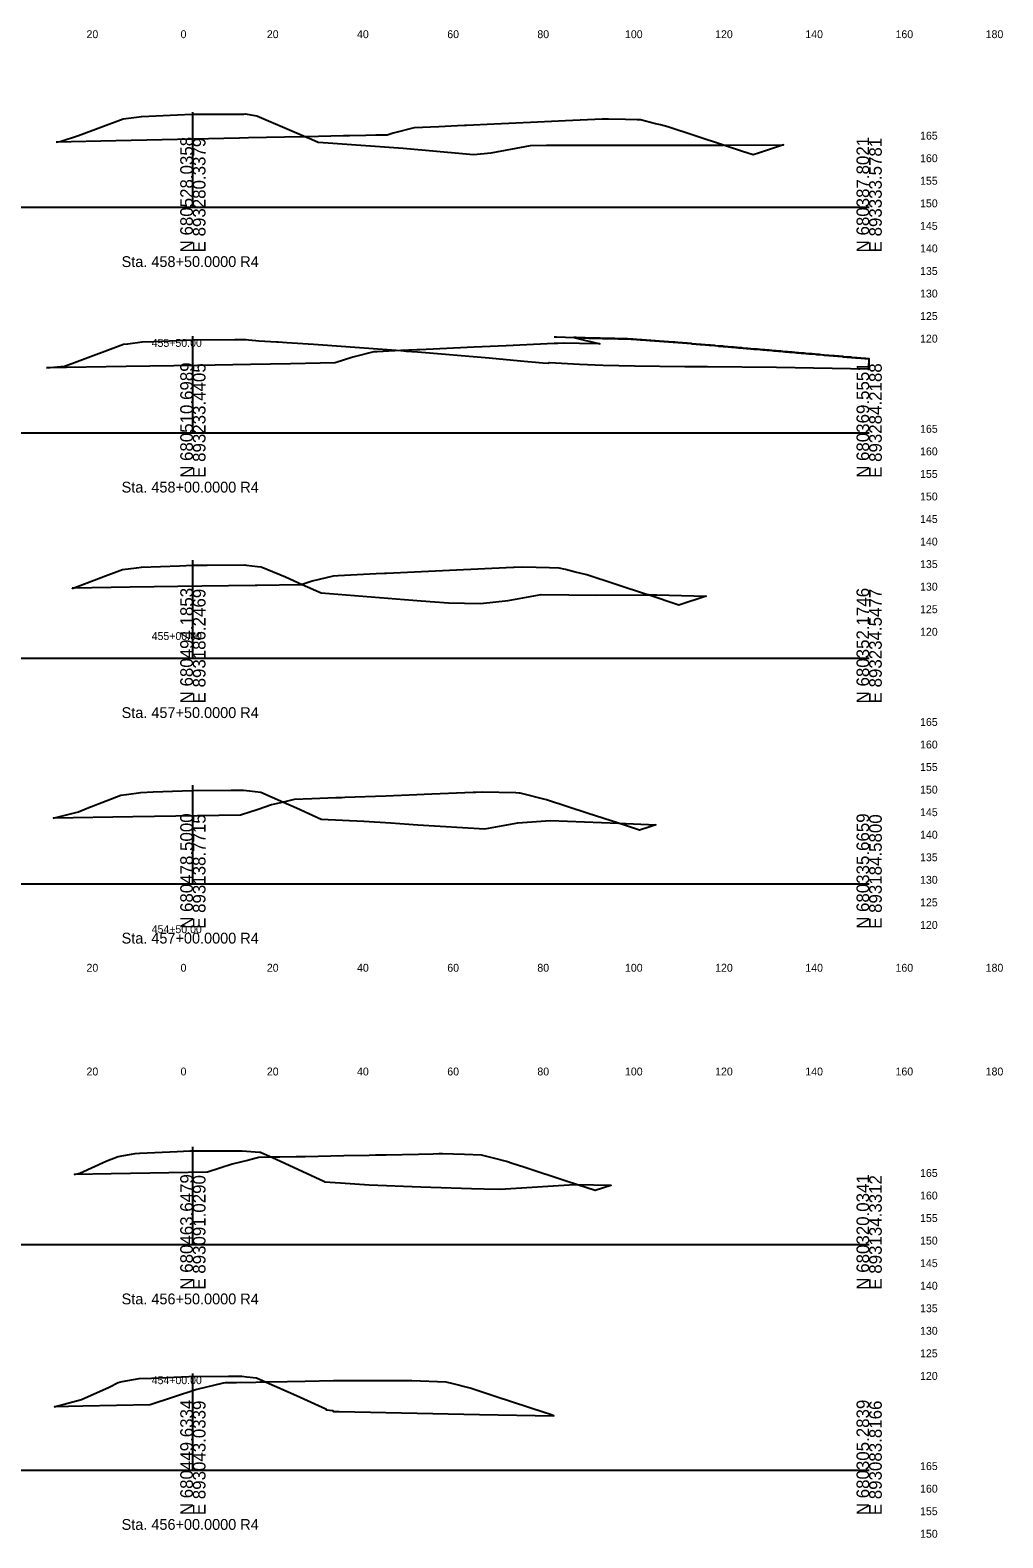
# Model space of a CAD drawing. Extents: x 21059 to 22955, y 6470 to 17494.
# Drawn here: x 21608.7 to 21824.5, y 7499.8 to 7834.1 of the extents above; entities that cross this region are included whole.
import ezdxf

# ---------------------------------------------------------------- set-up
doc = ezdxf.new("R2010")
doc.units = 0
for name, color, linetype in [('CONST_DCH', 7, 'Continuous'), ('Draft_XS_Grid', 7, 'Continuous'), ('Draft_XS_Text', 7, 'Continuous'), ('DTM CONTOURS_MAJOR', 7, 'Continuous'), ('SLOPE_STAKES_FILL', 7, 'Continuous'), ('X_PROFILES_1', 7, 'Continuous'), ('XS_P_TX_CLEARZONE', 7, 'Continuous'), ('XS_SHEET_EW_TX_VOLUME', 7, 'Continuous')]:
    doc.layers.add(name, color=color, linetype=linetype)

msp = doc.modelspace()

# ---------------------------------------------------------------- linework, layer by layer
at = {"layer": 'DTM CONTOURS_MAJOR'}
for p, q in [((21644.84, 7794.84), (21644.84, 7815.91)), ((21494.84, 7794.84), (21644.84, 7794.84)), ((21644.84, 7794.84), (21794.84, 7794.84)), ((21644.84, 7744.84), (21644.84, 7766.24)), ((21494.84, 7744.84), (21644.84, 7744.84)), ((21644.84, 7744.84), (21794.84, 7744.84)), ((21644.84, 7694.84), (21644.84, 7716.56)), ((21494.84, 7694.84), (21644.84, 7694.84)), ((21644.84, 7694.84), (21794.84, 7694.84)), ((21644.84, 7644.84), (21644.84, 7666.7)), ((21494.84, 7644.84), (21644.84, 7644.84)), ((21644.84, 7644.84), (21794.84, 7644.84)), ((21644.84, 7564.84), (21644.84, 7586.54)), ((21494.84, 7564.84), (21644.84, 7564.84)), ((21644.84, 7564.84), (21794.84, 7564.84)), ((21644.84, 7514.84), (21644.84, 7536.27)), ((21494.84, 7514.84), (21644.84, 7514.84)), ((21644.84, 7514.84), (21794.84, 7514.84))]:
    msp.add_line(p, q, dxfattribs=at)
at = {"layer": 'XS_P_TX_CLEARZONE'}
msp.add_lwpolyline([(21724.99, 7766.12), (21725.52, 7766.11), (21725.53, 7766.11), (21731.39, 7765.87), (21732.01, 7765.86), (21732.64, 7765.85), (21733.21, 7765.82), (21733.84, 7765.81), (21734.49, 7765.8), (21735.16, 7765.79), (21735.69, 7765.77), (21736.36, 7765.76), (21737.06, 7765.75), (21737.57, 7765.73), (21738.27, 7765.72), (21738.45, 7765.71), (21739.18, 7765.7), (21739.2, 7765.7), (21739.46, 7765.7), (21740.21, 7765.69), (21740.46, 7765.68), (21741.23, 7765.67), (21742.03, 7765.61), (21742.24, 7765.6), (21742.44, 7765.58), (21743.26, 7765.52), (21744.11, 7765.46), (21744.27, 7765.45), (21744.43, 7765.44), (21745.29, 7765.38), (21746.18, 7765.31), (21746.3, 7765.3), (21746.42, 7765.3), (21747.32, 7765.23), (21747.41, 7765.22), (21748.33, 7765.16), (21749.29, 7765.09), (21749.35, 7765.09), (21749.4, 7765.08), (21750.36, 7765.01), (21751.37, 7764.94), (21751.38, 7764.94), (21751.38, 7764.94), (21751.73, 7764.91), (21752.38, 7764.86), (21752.39, 7764.86), (21752.41, 7764.86), (21753.41, 7764.77), (21753.44, 7764.77), (21754.42, 7764.68), (21755.36, 7764.6), (21755.44, 7764.6), (21755.52, 7764.59), (21756.45, 7764.51), (21757.34, 7764.43), (21757.47, 7764.42), (21757.59, 7764.41), (21758.48, 7764.34), (21759.33, 7764.26), (21759.5, 7764.25), (21759.67, 7764.23), (21760.51, 7764.16), (21761.32, 7764.09), (21761.53, 7764.07), (21762.31, 7764.01), (21762.54, 7763.99), (21762.78, 7763.97), (21763.56, 7763.9), (21764.3, 7763.84), (21764.57, 7763.81), (21765.29, 7763.75), (21765.59, 7763.73), (21765.89, 7763.7), (21766.6, 7763.64), (21766.93, 7763.61), (21767.61, 7763.55), (21768.27, 7763.5), (21768.63, 7763.47), (21769.26, 7763.41), (21769.64, 7763.38), (21770.04, 7763.35), (21770.66, 7763.29), (21771.25, 7763.24), (21771.67, 7763.21), (21772.12, 7763.17), (21772.69, 7763.12), (21773.24, 7763.07), (21773.7, 7763.03), (21774.19, 7762.99), (21774.72, 7762.94), (21775.23, 7762.9), (21775.73, 7762.86), (21776.22, 7762.82), (21776.75, 7762.77), (21777.21, 7762.73), (21777.76, 7762.68), (21778.34, 7762.63), (21778.78, 7762.6), (21779.38, 7762.55), (21779.79, 7762.51), (21780.19, 7762.48), (21780.81, 7762.42), (21781.45, 7762.37), (21781.82, 7762.34), (21782.18, 7762.31), (21782.84, 7762.25), (21783.17, 7762.22), (21783.85, 7762.16), (21784.56, 7762.1), (21784.87, 7762.08), (21785.16, 7762.05), (21785.88, 7761.99), (21786.15, 7761.97), (21786.9, 7761.9), (21787.15, 7761.88), (21787.91, 7761.81), (21788.14, 7761.8), (21788.93, 7761.73), (21789.13, 7761.71), (21789.94, 7761.64), (21790.13, 7761.63), (21790.96, 7761.55), (21791.83, 7761.48), (21791.97, 7761.47), (21792.11, 7761.45), (21792.99, 7761.38), (21793.9, 7761.3), (21794, 7761.29), (21794.1, 7761.28), (21794.84, 7761.22)], dxfattribs=at)
at = {"layer": 'XS_SHEET_EW_TX_VOLUME'}
for points in [[(21614.48, 7809.3), (21615.43, 7809.4), (21619.47, 7810.79), (21629.41, 7814.46), (21632.37, 7814.85), (21633.45, 7815), (21641.46, 7815.32), (21644.62, 7815.45), (21654.38, 7815.47), (21656.12, 7815.49), (21656.41, 7815.53), (21658.57, 7815.2), (21659.03, 7815.13), (21669.91, 7810.48), (21669.18, 7810.46), (21657.21, 7810.21), (21655.18, 7810.17), (21651.71, 7810.09), (21627.74, 7809.58)], [(21669.91, 7810.48), (21671.17, 7809.94), (21672.66, 7809.28), (21674.83, 7809.12), (21691.51, 7807.97), (21705.47, 7806.7), (21707.1, 7806.53), (21710.99, 7806.93), (21719.71, 7808.52), (21723.31, 7808.59), (21732.61, 7808.6), (21758.84, 7808.62), (21762.53, 7808.63), (21750.21, 7812.68), (21748.59, 7813.09), (21747.46, 7813.37), (21744.09, 7814.2), (21743.38, 7814.22), (21740.81, 7814.27), (21737.04, 7814.36), (21736, 7814.38), (21735.65, 7814.37), (21733.97, 7814.29), (21727.48, 7813.99), (21719.76, 7813.63), (21711.7, 7813.26), (21705.55, 7812.98), (21705.08, 7812.96), (21703.52, 7812.88), (21699.41, 7812.69), (21693.94, 7812.44), (21689.3, 7811.3), (21687.95, 7810.86), (21685.45, 7810.81), (21683.17, 7810.76), (21679.59, 7810.68), (21678.27, 7810.66)], [(21762.53, 7808.63), (21775.88, 7808.66), (21770.51, 7806.89), (21769.15, 7806.44), (21766.77, 7807.23)], [(21690.99, 7763.05), (21691.07, 7763.05), (21692.13, 7762.95), (21694.67, 7762.75), (21710.53, 7761.43), (21717.49, 7760.81), (21722.47, 7760.35), (21723.75, 7760.3), (21723.96, 7760.4), (21730.63, 7760.04), (21735.86, 7759.84), (21742.82, 7759.67), (21753.97, 7759.51), (21758.99, 7759.53), (21774.3, 7759.37), (21794.84, 7759.01), (21794.84, 7761.22), (21794.1, 7761.28), (21794, 7761.29), (21793.9, 7761.3), (21792.99, 7761.38), (21792.11, 7761.45), (21791.97, 7761.47), (21791.83, 7761.48), (21790.96, 7761.55), (21790.79, 7761.57), (21789.94, 7761.64), (21789.13, 7761.71), (21788.93, 7761.73), (21788.14, 7761.8), (21787.91, 7761.81), (21787.15, 7761.88), (21786.9, 7761.9), (21786.64, 7761.92), (21785.88, 7761.99), (21785.6, 7762.01), (21784.87, 7762.08), (21784.17, 7762.14), (21783.85, 7762.16), (21783.17, 7762.22), (21782.84, 7762.25), (21782.18, 7762.31), (21781.82, 7762.34), (21781.45, 7762.37), (21780.81, 7762.42), (21780.42, 7762.46), (21779.79, 7762.51), (21779.2, 7762.56), (21778.78, 7762.6), (21778.34, 7762.63), (21777.76, 7762.68), (21777.21, 7762.73), (21776.75, 7762.77), (21776.27, 7762.81), (21775.73, 7762.86), (21775.23, 7762.9), (21774.72, 7762.94), (21774.23, 7762.99), (21773.7, 7763.03), (21773.24, 7763.07), (21772.69, 7763.12), (21772.12, 7763.17), (21771.67, 7763.21), (21771.08, 7763.26), (21770.66, 7763.29), (21770.04, 7763.35), (21769.64, 7763.38), (21769.26, 7763.41), (21768.63, 7763.47), (21767.97, 7763.52), (21767.61, 7763.55), (21766.93, 7763.61), (21766.6, 7763.64), (21765.89, 7763.7), (21765.59, 7763.73), (21764.85, 7763.79), (21764.57, 7763.81), (21764.3, 7763.84), (21763.56, 7763.9), (21762.78, 7763.97), (21762.54, 7763.99), (21762.31, 7764.01), (21761.53, 7764.07), (21760.71, 7764.15), (21760.51, 7764.16), (21759.67, 7764.23), (21759.5, 7764.25), (21759.33, 7764.26), (21758.48, 7764.34), (21757.59, 7764.41), (21757.47, 7764.42), (21757.34, 7764.43), (21756.45, 7764.51), (21755.52, 7764.59), (21755.44, 7764.6), (21754.48, 7764.68), (21754.42, 7764.68), (21754.36, 7764.69), (21753.41, 7764.77), (21753.37, 7764.77), (21752.39, 7764.86), (21752.38, 7764.86), (21751.73, 7764.91), (21751.38, 7764.94), (21751.38, 7764.94), (21750.39, 7765.01), (21750.36, 7765.01), (21749.4, 7765.08), (21749.35, 7765.09), (21749.29, 7765.09), (21748.33, 7765.16), (21747.41, 7765.22), (21747.32, 7765.23), (21746.42, 7765.3), (21746.3, 7765.3), (21745.42, 7765.37), (21745.29, 7765.38), (21744.43, 7765.44), (21744.27, 7765.45), (21744.11, 7765.46), (21743.26, 7765.52), (21742.44, 7765.58), (21742.24, 7765.6), (21742.03, 7765.61), (21741.23, 7765.67), (21740.46, 7765.68), (21740.21, 7765.69), (21739.46, 7765.7), (21739.2, 7765.7), (21739.18, 7765.7), (21738.45, 7765.71), (21738.27, 7765.72), (21737.57, 7765.73), (21737.06, 7765.75), (21736.36, 7765.76), (21735.69, 7765.77), (21735.16, 7765.79), (21734.49, 7765.8), (21733.84, 7765.81), (21729.83, 7765.93), (21729.35, 7765.95), (21731.68, 7765.38), (21733.3, 7764.98), (21735.1, 7764.53), (21730.59, 7764.64), (21727.01, 7764.72), (21725.78, 7764.66), (21724.98, 7764.62), (21714.36, 7764.13), (21710.77, 7763.97), (21707.26, 7763.8), (21696.55, 7763.31), (21695.2, 7763.25), (21694.52, 7763.22)], [(21612.38, 7759.21), (21616.4, 7759.64), (21618.56, 7760.45), (21629.43, 7764.46), (21630.38, 7764.59), (21633.57, 7765.01), (21636.15, 7765.11), (21644.81, 7765.45), (21654.13, 7765.5), (21656.68, 7765.52), (21657.19, 7765.45), (21658.77, 7765.31), (21659.45, 7765.2), (21663.42, 7765), (21663.78, 7764.99), (21665.65, 7764.88), (21671.62, 7764.51), (21672.6, 7764.42), (21690.99, 7763.05), (21685.7, 7762.81), (21684.95, 7762.77), (21680.31, 7761.64), (21676.43, 7760.37), (21666.52, 7760.16), (21657.59, 7759.97), (21645.86, 7759.77), (21630.03, 7759.51)], [(21618.22, 7710.38), (21618.3, 7710.39), (21625.47, 7713.11), (21629.24, 7714.5), (21632.36, 7714.9), (21633.46, 7715.04), (21641.85, 7715.35), (21644.81, 7715.47), (21647.98, 7715.48), (21656.33, 7715.53), (21656.66, 7715.49), (21659.19, 7715.19), (21659.99, 7715.12), (21665.38, 7712.87), (21669.11, 7711.23), (21668.9, 7711.16), (21659.13, 7710.99), (21659.04, 7710.99), (21658.62, 7710.99), (21646.83, 7710.81), (21630.95, 7710.57)], [(21669.11, 7711.23), (21673.31, 7709.38), (21695.47, 7707.57), (21701.52, 7707.14), (21708.64, 7706.95), (21714.77, 7707.67), (21722.06, 7709.01), (21734.4, 7708.84), (21745.81, 7708.87), (21745.49, 7708.97), (21732.23, 7713.34), (21729.44, 7714.03), (21727.48, 7714.51), (21726.11, 7714.85), (21723.94, 7714.9), (21718.02, 7715.03), (21716.14, 7714.95), (21715.99, 7714.94), (21715.85, 7714.93), (21701.78, 7714.28), (21687.76, 7713.63), (21687.56, 7713.62), (21687.35, 7713.61), (21685.53, 7713.53), (21677.04, 7713.13), (21675.96, 7713.08), (21671.31, 7711.94)], [(21618.08, 7710.38), (21618.08, 7710.37), (21618.22, 7710.38)], [(21745.81, 7708.87), (21747.73, 7708.87), (21758.69, 7708.62), (21752.61, 7706.63)], [(21613.87, 7659.35), (21619.5, 7660.76), (21621.41, 7661.62), (21628.89, 7664.46), (21630.1, 7664.67), (21633.31, 7665.09), (21636, 7665.2), (21644.63, 7665.51), (21653.3, 7665.56), (21656.07, 7665.58), (21657.4, 7665.47), (21659.91, 7665.17), (21664.96, 7662.95), (21662.31, 7662.31), (21659.29, 7661.32), (21655.4, 7660.05), (21631.51, 7659.65)], [(21664.96, 7662.95), (21667.83, 7661.69), (21673.27, 7659.2), (21682.78, 7658.73), (21688.74, 7658.32), (21694.76, 7657.92), (21709.59, 7657.04), (21716.9, 7658.38), (21724.14, 7658.87), (21739.21, 7658.25), (21732.53, 7660.44), (21723.24, 7663.48), (21717.45, 7664.91), (21717.25, 7664.96), (21716.49, 7664.97), (21709.03, 7665.17), (21707.62, 7665.11), (21707, 7665.08), (21697.83, 7664.71), (21692.78, 7664.5), (21687.61, 7664.29), (21678.56, 7663.94), (21677.87, 7663.92), (21676.53, 7663.86), (21671.19, 7663.67), (21667.27, 7663.52)], [(21739.21, 7658.25), (21747.54, 7657.91), (21745.95, 7657.39), (21743.89, 7656.72)], [(21618.5, 7580.37), (21619.73, 7580.67), (21625.76, 7583.4), (21628.24, 7584.34), (21632.02, 7585), (21633.07, 7585.14), (21641.38, 7585.5), (21644.19, 7585.6), (21647, 7585.62), (21655.76, 7585.66), (21659.6, 7585.36), (21659.84, 7585.33), (21660.16, 7585.19), (21662.32, 7584.19), (21659.46, 7584.13), (21657.45, 7583.64), (21657.22, 7583.58), (21653.55, 7582.68), (21648.07, 7580.87), (21626.69, 7580.51)], [(21662.32, 7584.19), (21674.05, 7578.8), (21674.06, 7578.78), (21677.62, 7578.53), (21683.96, 7578.09), (21695.39, 7577.66), (21706.61, 7577.24), (21709.43, 7577.18), (21713, 7577.13), (21729.47, 7578.18), (21729.91, 7578.17), (21727.85, 7578.85), (21718.26, 7582), (21715.89, 7582.77), (21714.38, 7583.27), (21711.8, 7583.9), (21708.85, 7584.63), (21705.11, 7584.78), (21700.18, 7584.97), (21699.41, 7584.95), (21698.16, 7584.92), (21694.85, 7584.84), (21687.74, 7584.69), (21685.38, 7584.64), (21683.97, 7584.61), (21678.3, 7584.5), (21669.77, 7584.33), (21668.09, 7584.3), (21667.75, 7584.29), (21664.1, 7584.23)], [(21729.91, 7578.17), (21737.57, 7577.98), (21737.57, 7577.95), (21734.07, 7576.81)], [(21614.05, 7528.88), (21620.15, 7530.47), (21626.24, 7533.22), (21628.3, 7534.26), (21629.14, 7534.46), (21632.92, 7535.12), (21635.68, 7535.24), (21643.93, 7535.6), (21652.74, 7535.65), (21655.67, 7535.68), (21656.83, 7535.54), (21658.95, 7535.29), (21661.13, 7534.33), (21659.84, 7534.3), (21658.81, 7534.28), (21654.54, 7534.2), (21654.27, 7534.19), (21653.71, 7534.18), (21652, 7534.15), (21651.58, 7534.14), (21645.69, 7532.68), (21635.35, 7529.27), (21620.42, 7529)], [(21661.13, 7534.33), (21667.82, 7531.38), (21674.3, 7528.4), (21674.38, 7528.19), (21675.86, 7528.08), (21676.02, 7527.85), (21677.3, 7527.8), (21708.44, 7527.15), (21724.91, 7526.9), (21724.16, 7527.15), (21722.78, 7527.6), (21712.11, 7531.11), (21706.34, 7533.01), (21702.56, 7533.94), (21701.02, 7534.32), (21693.42, 7534.61), (21692.19, 7534.66), (21691.99, 7534.66), (21690.17, 7534.65), (21689.73, 7534.65), (21688.66, 7534.65), (21679.72, 7534.62), (21676.01, 7534.62), (21669.72, 7534.5), (21661.86, 7534.34), (21661.45, 7534.33)]]:
    msp.add_lwpolyline(points, close=True, dxfattribs=at)

# ---------------------------------------------------------------- texts
at = {"layer": 'CONST_DCH'}
for p in [(21687.91, 7810.8), (21687.91, 7810.8), (21769.11, 7806.38), (21769.11, 7806.38), (21676.39, 7760.31), (21676.39, 7760.31), (21760.86, 7756.48), (21760.86, 7756.48), (21668.86, 7711.1), (21668.86, 7711.1), (21752.58, 7706.57), (21752.58, 7706.57), (21655.36, 7659.99), (21655.36, 7659.99), (21743.85, 7656.66), (21743.85, 7656.66), (21648.03, 7580.81), (21648.03, 7580.81), (21734.04, 7576.75), (21734.04, 7576.75), (21635.31, 7529.21), (21635.31, 7529.21), (21724.88, 7526.84), (21724.88, 7526.84)]:
    msp.add_text('X', height=0.12, dxfattribs=at).set_placement(p)
at = {"layer": 'Draft_XS_Grid'}
for s, p in [('  165  ', (21804.84, 7809.84)), ('  160  ', (21804.84, 7804.84)), ('  155  ', (21804.84, 7799.84)), ('  150  ', (21804.84, 7794.84)), ('  145  ', (21804.84, 7789.84)), ('  140  ', (21804.84, 7784.84)), ('  135  ', (21804.84, 7779.84)), ('  130  ', (21804.84, 7774.84)), ('  125  ', (21804.84, 7769.84)), ('  120  ', (21804.84, 7764.84)), ('  165  ', (21804.84, 7744.84)), ('  160  ', (21804.84, 7739.84)), ('  155  ', (21804.84, 7734.84)), ('  150  ', (21804.84, 7729.84)), ('  145  ', (21804.84, 7724.84)), ('  140  ', (21804.84, 7719.84)), ('  135  ', (21804.84, 7714.84)), ('  130  ', (21804.84, 7709.84)), ('  125  ', (21804.84, 7704.84)), ('  120  ', (21804.84, 7699.84)), ('  165  ', (21804.84, 7679.84)), ('  160  ', (21804.84, 7674.84)), ('  155  ', (21804.84, 7669.84)), ('  150  ', (21804.84, 7664.84)), ('  145  ', (21804.84, 7659.84)), ('  140  ', (21804.84, 7654.84)), ('  135  ', (21804.84, 7649.84)), ('  130  ', (21804.84, 7644.84)), ('  125  ', (21804.84, 7639.84)), ('  120  ', (21804.84, 7634.84)), ('  165  ', (21804.84, 7579.84)), ('  160  ', (21804.84, 7574.84)), ('  155  ', (21804.84, 7569.84)), ('  150  ', (21804.84, 7564.84)), ('  145  ', (21804.84, 7559.84)), ('  140  ', (21804.84, 7554.84)), ('  135  ', (21804.84, 7549.84)), ('  130  ', (21804.84, 7544.84)), ('  125  ', (21804.84, 7539.84)), ('  120  ', (21804.84, 7534.84)), ('  165  ', (21804.84, 7514.84)), ('  160  ', (21804.84, 7509.84)), ('  155  ', (21804.84, 7504.84)), ('  150  ', (21804.84, 7499.84))]:
    msp.add_text(s, height=1.75, dxfattribs=at).set_placement(p)
at = {"layer": 'Draft_XS_Text'}
for s, p in [('  20  ', (21619.95, 7832.34)), ('  0  ', (21640.81, 7832.34)), ('  0  ', (21640.81, 7832.34)), ('  20  ', (21659.95, 7832.34)), ('  40  ', (21679.95, 7832.34)), ('  60  ', (21699.97, 7832.34)), ('  80  ', (21719.95, 7832.34)), ('  100  ', (21739.39, 7832.34)), ('  120  ', (21759.39, 7832.34)), ('  140  ', (21779.39, 7832.34)), ('  160  ', (21799.4, 7832.34)), ('  180  ', (21819.39, 7832.34)), ('  20  ', (21619.95, 7625.34)), ('  0  ', (21640.81, 7625.34)), ('  0  ', (21640.81, 7625.34)), ('  20  ', (21659.95, 7625.34)), ('  40  ', (21679.95, 7625.34)), ('  60  ', (21699.97, 7625.34)), ('  80  ', (21719.95, 7625.34)), ('  100  ', (21739.39, 7625.34)), ('  120  ', (21759.39, 7625.34)), ('  140  ', (21779.39, 7625.34)), ('  160  ', (21799.4, 7625.34)), ('  180  ', (21819.39, 7625.34)), ('  20  ', (21619.95, 7602.34)), ('  0  ', (21640.81, 7602.34)), ('  0  ', (21640.81, 7602.34)), ('  20  ', (21659.95, 7602.34)), ('  40  ', (21679.95, 7602.34)), ('  60  ', (21699.97, 7602.34)), ('  80  ', (21719.95, 7602.34)), ('  100  ', (21739.39, 7602.34)), ('  120  ', (21759.39, 7602.34)), ('  140  ', (21779.39, 7602.34)), ('  160  ', (21799.4, 7602.34)), ('  180  ', (21819.39, 7602.34))]:
    msp.add_text(s, height=1.75, dxfattribs=at).set_placement(p)
at = {"layer": 'DTM CONTOURS_MAJOR'}
for s, p in [('N 680528.0358', (21644.84, 7784.84)), ('E 893280.3379', (21647.64, 7784.84)), ('N 680387.8021', (21794.84, 7784.84)), ('E 893333.5781', (21797.64, 7784.84)), ('N 680510.6989', (21644.84, 7734.84)), ('E 893233.4405', (21647.64, 7734.84)), ('N 680369.5551', (21794.84, 7734.84)), ('E 893284.2188', (21797.64, 7734.84)), ('N 680494.1853', (21644.84, 7684.84)), ('E 893186.2469', (21647.64, 7684.84)), ('N 680352.1746', (21794.84, 7684.84)), ('E 893234.5477', (21797.64, 7684.84)), ('N 680478.5000', (21644.84, 7634.84)), ('E 893138.7715', (21647.64, 7634.84)), ('N 680335.6659', (21794.84, 7634.84)), ('E 893184.5800', (21797.64, 7634.84)), ('N 680463.6479', (21644.84, 7554.84)), ('E 893091.0290', (21647.64, 7554.84)), ('N 680320.0341', (21794.84, 7554.84)), ('E 893134.3312', (21797.64, 7554.84)), ('N 680449.6334', (21644.84, 7504.84)), ('E 893043.0339', (21647.64, 7504.84)), ('N 680305.2839', (21794.84, 7504.84)), ('E 893083.8166', (21797.64, 7504.84))]:
    msp.add_text(s, height=2.8, rotation=90, dxfattribs=at).set_placement(p)
at = {"layer": 'SLOPE_STAKES_FILL'}
for s, p in [('  455+50.00  ', (21634.4, 7763.89)), ('  455+00.00  ', (21634.4, 7698.89)), ('  454+50.00  ', (21634.4, 7633.89)), ('  454+00.00  ', (21634.4, 7533.89))]:
    msp.add_text(s, height=1.75, dxfattribs=at).set_placement(p)
at = {"layer": 'X_PROFILES_1'}
for s, p in [('Sta. 458+50.0000 R4', (21629.03, 7781.59)), ('Sta. 458+00.0000 R4', (21629.03, 7731.59)), ('Sta. 457+50.0000 R4', (21629.03, 7681.59)), ('Sta. 457+00.0000 R4', (21629.03, 7631.59)), ('Sta. 456+50.0000 R4', (21629.03, 7551.59)), ('Sta. 456+00.0000 R4', (21629.03, 7501.59))]:
    msp.add_text(s, height=2.4, dxfattribs=at).set_placement(p)

doc.saveas('drawing.dxf')
